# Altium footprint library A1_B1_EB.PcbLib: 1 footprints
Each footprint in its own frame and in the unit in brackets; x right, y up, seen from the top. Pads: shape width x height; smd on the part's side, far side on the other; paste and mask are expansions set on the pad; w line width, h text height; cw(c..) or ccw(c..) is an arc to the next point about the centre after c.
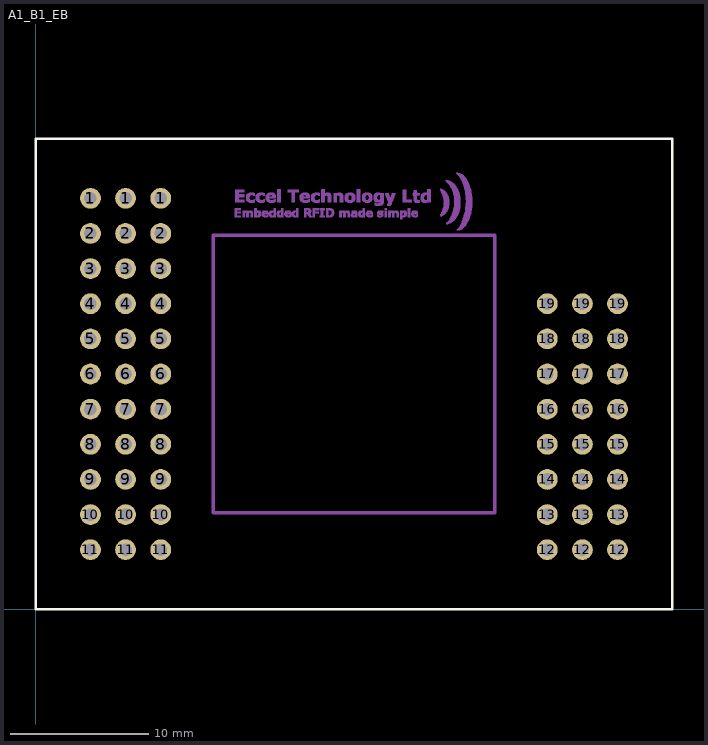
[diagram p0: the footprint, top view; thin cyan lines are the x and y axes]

## A1_B1_EB [mm]
pads (57):
  round 1.5 hole 0.9: 1(3.95,29.7) 1(6.49,29.7) 1(9.03,29.7) 2(3.95,27.16) 2(6.49,27.16) 2(9.03,27.16) 3(3.95,24.62) 3(6.49,24.62) 3(9.03,24.62) 4(3.95,22.08) 4(6.49,22.08) 4(9.03,22.08) 5(3.95,19.54) 5(6.49,19.54) 5(9.03,19.54) 6(3.95,17) 6(6.49,17) 6(9.03,17) 7(3.95,14.46) 7(6.49,14.46) 7(9.03,14.46) 8(3.95,11.92) 8(6.49,11.92) 8(9.03,11.92) 9(3.95,9.38) 9(6.49,9.38) 9(9.03,9.38) 10(3.95,6.84) 10(6.49,6.84) 10(9.03,6.84) 11(3.95,4.3) 11(6.49,4.3) 11(9.03,4.3) 12(36.97,4.3) 12(39.51,4.3) 12(42.05,4.3) 13(36.97,6.84) 13(39.51,6.84) 13(42.05,6.84) 14(36.97,9.38) 14(39.51,9.38) 14(42.05,9.38) 15(36.97,11.92) 15(39.51,11.92) 15(42.05,11.92) 16(36.97,14.46) 16(39.51,14.46) 16(42.05,14.46) 17(36.97,17) 17(39.51,17) 17(42.05,17) 18(36.97,19.54) 18(39.51,19.54) 18(42.05,19.54) 19(36.97,22.08) 19(39.51,22.08) 19(42.05,22.08)
Top Overlay:
  lines w0.2: 0,0 46,0 46,34 0,34 0,0
Assembly Text Top:
  drawing of 1811 lines, arcs and shapes, not listed
  text "GND" at 5.728,28.113 h0.61
  text "GND" at 5.715,2.54 h0.61
  text "GND" at 38.735,2.54 h0.61
  text "nRST" at 5.347,25.573 h0.61
  text "nSLEEP" at 4.801,23.063 h0.61
  text "nPWRDN" at 4.775,20.493 h0.61
  text "SDA/IO3" at 4.775,17.953 h0.61
  text "SCL/IO2" at 4.775,15.413 h0.61
  text "MISO/IO1" at 4.775,12.872 h0.61
  text "MOSI/IO0" at 4.775,10.333 h0.61
  text "CS/TX" at 5.093,7.793 h0.61
  text "CLK/RX" at 4.775,5.253 h0.61
  text "GND" at 38.748,20.493 h0.61
  text "VDD" at 38.748,17.952 h0.61
  text "LED" at 38.684,15.418 h0.61
  text "NC" at 39.002,12.873 h0.61
  text "AD0/IDAC" at 37.478,10.333 h0.61
  text "AD1/CMP" at 37.605,7.793 h0.61
  text "AD2/ADC" at 37.478,5.253 h0.61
